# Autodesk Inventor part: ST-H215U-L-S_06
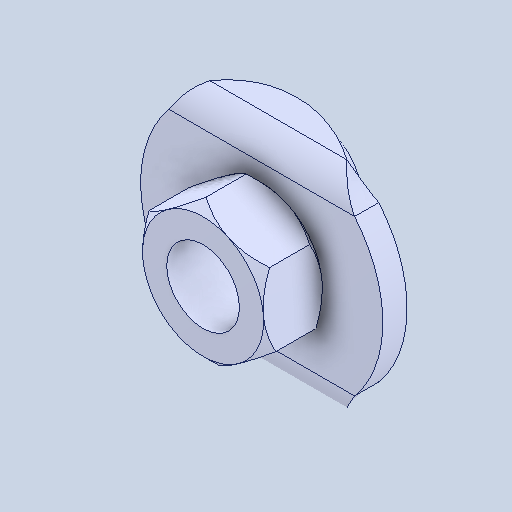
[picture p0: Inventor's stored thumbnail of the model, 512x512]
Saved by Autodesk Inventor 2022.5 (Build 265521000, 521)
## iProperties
Created: 2024-07
Part Number: ST-H215U-L-S_06
Material: 一般
Document SubType Name: Modeling
Designer: ImaoCorp
Density: 1 g/cm^3
Appearance: 既定
Author: ImaoCorp
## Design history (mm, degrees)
feature "ST-H215U-L-S_06"
node "ソリッド1"
